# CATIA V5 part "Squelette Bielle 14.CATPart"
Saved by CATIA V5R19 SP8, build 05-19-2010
Part number: Squelette bielle 14
Publications: "Droite D (bielle 14)", "Droite A (bielle 14)", "Droite AD (bielle 14)", "Plan.3", "Plan.4"
Bounding box of the stored display mesh (mm): x 1 to 39, y 68 to 89, z -50 to 50
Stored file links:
  G:\EU_thinkMotion\CFAO_2010\MMS_groupe3\MMS_groupe3\A reprendre\lpastor\lpastor\Squelette Bielle 14.CATPart
  C:\Users\Loïc\Documents\IFMA\Cours 2A\CFAO\Thinkmotion\Fourche avant.CATProduct
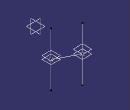
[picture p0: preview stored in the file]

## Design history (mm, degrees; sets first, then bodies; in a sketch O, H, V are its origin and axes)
Set1
  Point1 "A": linked copy from another document
  Point2 "D": linked copy from another document
Set2 "Set géométrique bielle 14"
  Line1 "Droite A (bielle 14)": type PtDir, RefPoint Point1, Direction xy-plane, Start -50, End 50
  Line2 "Droite D (bielle 14)": type PtDir, RefPoint Point2, Direction xy-plane, Start -50, End 50
  Line3 "Droite AD (bielle 14)": type PtPt, FirstPoint Point1, SecondPoint Point2
  Plane1: type Normal, Curve Line1, RefPoint Point1
  Plane2: type Normal, Curve Line2, RefPoint Point2
  Plane3: type Offset, RefPlane Plane1, Offset 6
  Plane4: type Offset, RefPlane Plane2, Offset 8
Body1 (main body)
